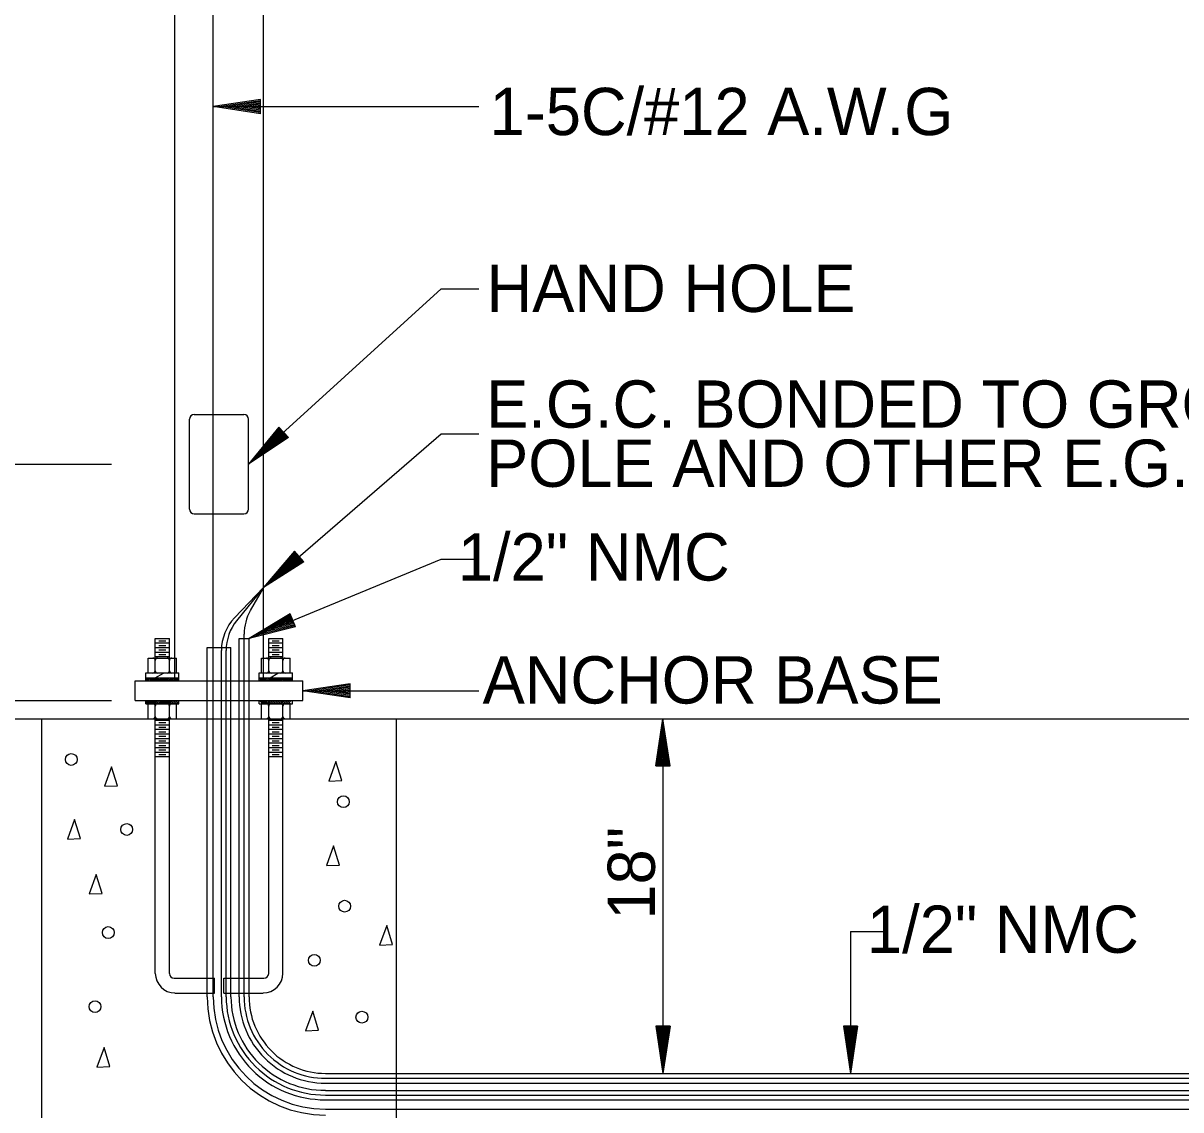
# Model space of a CAD drawing. Extents: x 1369885 to 1370886, y 379976 to 380616.
# Drawn here: x 1369995.4 to 1370105.6, y 380406.2 to 380509.6 of the extents above; entities that cross this region are included whole.
import ezdxf

# ---------------------------------------------------------------- set-up
doc = ezdxf.new("R2010")
doc.units = 0
doc.layers.add('R_Draft', color=7, linetype='Continuous')

msp = doc.modelspace()

# ---------------------------------------------------------------- linework, layer by layer
at = {"layer": 'R_Draft'}
for p, q in [((1370009.8, 380447), (1370009.8, 380537.68)), ((1370018.24, 380447), (1370018.24, 380537.68)), ((1370013.45, 380416.95), (1370013.45, 380515.9)), ((1370017.96, 380502.33), (1370013.46, 380501.65)), ((1370017.96, 380502.21), (1370014.21, 380501.65)), ((1370017.96, 380502.1), (1370014.98, 380501.65)), ((1370017.96, 380501.99), (1370015.73, 380501.65)), ((1370017.96, 380501.87), (1370016.5, 380501.65)), ((1370017.96, 380500.98), (1370017.96, 380502.33)), ((1370013.46, 380501.65), (1370038.75, 380501.65)), ((1370017.96, 380500.98), (1370013.46, 380501.65)), ((1370017.96, 380501.09), (1370014.21, 380501.65)), ((1370017.96, 380501.2), (1370014.98, 380501.65)), ((1370017.96, 380501.32), (1370015.73, 380501.65)), ((1370017.96, 380501.43), (1370016.5, 380501.65)), ((1370017.96, 380501.76), (1370017.25, 380501.65)), ((1370017.96, 380501.55), (1370017.25, 380501.65)), ((1370016.83, 380467.63), (1370035.14, 380484.32)), ((1370035.14, 380484.32), (1370038.75, 380484.32)), ((1370011.65, 380472.35), (1370016.38, 380472.35)), ((1370011.2, 380463.35), (1370011.2, 380471.9)), ((1370016.83, 380463.35), (1370016.83, 380471.9)), ((1370019.7, 380471.16), (1370016.83, 380467.63)), ((1370019.77, 380471.08), (1370017.38, 380468.14)), ((1370019.85, 380470.99), (1370017.96, 380468.66)), ((1370020.61, 380470.16), (1370019.7, 380471.16)), ((1370020.61, 380470.16), (1370016.83, 380467.63)), ((1370020.53, 380470.25), (1370017.38, 380468.14)), ((1370020.45, 380470.33), (1370017.96, 380468.66)), ((1370018.24, 380455.89), (1370035.14, 380470.51)), ((1370019.93, 380470.91), (1370018.51, 380469.16)), ((1370020.38, 380470.42), (1370018.51, 380469.16)), ((1370020, 380470.83), (1370019.07, 380469.68)), ((1370020.3, 380470.5), (1370019.07, 380469.68)), ((1370020.08, 380470.74), (1370019.63, 380470.18)), ((1370020.22, 380470.59), (1370019.63, 380470.18)), ((1370035.14, 380470.51), (1370038.75, 380470.51)), ((1369990.67, 380467.63), (1370003.78, 380467.63)), ((1370011.65, 380462.9), (1370016.38, 380462.9)), ((1370021.18, 380459.36), (1370018.24, 380455.89)), ((1370021.25, 380459.28), (1370018.8, 380456.38)), ((1370021.33, 380459.19), (1370019.38, 380456.89)), ((1370021.4, 380459.11), (1370019.95, 380457.39)), ((1370021.48, 380459.02), (1370020.52, 380457.89)), ((1370021.55, 380458.93), (1370021.09, 380458.38)), ((1370022.07, 380458.35), (1370021.18, 380459.36)), ((1370016.87, 380451.05), (1370035.14, 380458.59)), ((1370022.07, 380458.35), (1370018.24, 380455.89)), ((1370021.99, 380458.43), (1370018.8, 380456.38)), ((1370021.92, 380458.52), (1370019.38, 380456.89)), ((1370021.84, 380458.6), (1370019.95, 380457.39)), ((1370021.76, 380458.69), (1370020.52, 380457.89)), ((1370021.69, 380458.77), (1370021.09, 380458.38)), ((1370035.14, 380458.59), (1370038.75, 380458.59)), ((1370018.24, 380455.89), (1370015.49, 380453.01)), ((1370018.24, 380455.89), (1370015.69, 380452.73)), ((1370018.24, 380455.89), (1370016.98, 380453.69)), ((1370020.77, 380453.39), (1370016.87, 380451.05)), ((1370021.28, 380452.14), (1370020.77, 380453.39)), ((1370020.81, 380453.29), (1370017.56, 380451.34)), ((1370021.24, 380452.25), (1370017.56, 380451.34)), ((1370020.86, 380453.18), (1370018.28, 380451.63)), ((1370021.2, 380452.35), (1370018.28, 380451.63)), ((1370020.9, 380453.08), (1370018.97, 380451.92)), ((1370021.15, 380452.46), (1370018.97, 380451.92)), ((1370020.94, 380452.97), (1370019.67, 380452.21)), ((1370021.11, 380452.57), (1370019.67, 380452.21)), ((1370020.99, 380452.87), (1370020.37, 380452.5)), ((1370021.07, 380452.67), (1370020.37, 380452.5)), ((1370016.4, 380416.95), (1370016.4, 380451.46)), ((1370021.28, 380452.14), (1370016.87, 380451.05)), ((1370007.94, 380451.05), (1370009.29, 380451.05)), ((1370007.94, 380449.18), (1370007.94, 380451.05)), ((1370007.94, 380450.62), (1370009.29, 380450.62)), ((1370007.94, 380450.19), (1370009.29, 380450.19)), ((1370008.28, 380450.83), (1370008.95, 380450.83)), ((1370008.28, 380450.39), (1370008.95, 380450.39)), ((1370009.29, 380449.18), (1370009.29, 380451.05)), ((1370012.89, 380416.95), (1370012.89, 380450.19)), ((1370012.89, 380450.19), (1370015.14, 380450.19)), ((1370015.14, 380416.95), (1370015.14, 380450.19)), ((1370015.93, 380416.95), (1370015.93, 380451.05)), ((1370015.93, 380451.05), (1370016.87, 380451.05)), ((1370016.87, 380416.95), (1370016.87, 380451.05)), ((1370018.74, 380451.05), (1370020.09, 380451.05)), ((1370018.74, 380449.18), (1370018.74, 380451.05)), ((1370018.74, 380450.62), (1370020.09, 380450.62)), ((1370018.74, 380450.19), (1370020.09, 380450.19)), ((1370019.08, 380450.83), (1370019.75, 380450.83)), ((1370019.08, 380450.39), (1370019.75, 380450.39)), ((1370020.09, 380449.18), (1370020.09, 380451.05)), ((1370007.27, 380447.76), (1370007.27, 380449.18)), ((1370007.27, 380449.18), (1370009.97, 380449.18)), ((1370007.94, 380449.75), (1370009.29, 380449.75)), ((1370007.94, 380449.32), (1370009.29, 380449.32)), ((1370007.94, 380447.76), (1370007.94, 380449.18)), ((1370008.28, 380449.96), (1370008.95, 380449.96)), ((1370008.28, 380449.53), (1370008.95, 380449.53)), ((1370009.29, 380447.76), (1370009.29, 380449.18)), ((1370009.97, 380447.76), (1370009.97, 380449.18)), ((1370014.24, 380416.95), (1370014.24, 380449.9)), ((1370014.69, 380416.95), (1370014.69, 380449.91)), ((1370018.07, 380447.76), (1370018.07, 380449.18)), ((1370018.07, 380449.18), (1370020.77, 380449.18)), ((1370018.74, 380449.75), (1370020.09, 380449.75)), ((1370018.74, 380449.32), (1370020.09, 380449.32)), ((1370018.74, 380447.76), (1370018.74, 380449.18)), ((1370019.08, 380449.96), (1370019.75, 380449.96)), ((1370019.08, 380449.53), (1370019.75, 380449.53)), ((1370020.09, 380447.76), (1370020.09, 380449.18)), ((1370020.77, 380447.76), (1370020.77, 380449.18)), ((1370006.03, 380445.13), (1370006.03, 380447)), ((1370006.03, 380447), (1370022, 380447)), ((1370007.04, 380447), (1370007.04, 380447.76)), ((1370007.04, 380447.76), (1370010.19, 380447.76)), ((1370007.04, 380447.3), (1370010.19, 380447.3)), ((1370007.04, 380447.15), (1370007.2, 380447.3)), ((1370007.06, 380447), (1370007.36, 380447.3)), ((1370007.22, 380447), (1370007.52, 380447.3)), ((1370007.38, 380447), (1370007.68, 380447.3)), ((1370007.53, 380447), (1370007.83, 380447.3)), ((1370007.69, 380447), (1370007.94, 380447.25)), ((1370007.85, 380447), (1370007.94, 380447.09)), ((1370007.94, 380447.3), (1370008.73, 380447.74)), ((1370007.94, 380447.07), (1370008.17, 380447.3)), ((1370007.94, 380447.23), (1370008.01, 380447.3)), ((1370008.03, 380447), (1370008.33, 380447.3)), ((1370008.19, 380447), (1370008.49, 380447.3)), ((1370008.35, 380447), (1370008.65, 380447.3)), ((1370008.51, 380447), (1370008.81, 380447.3)), ((1370008.67, 380447), (1370008.97, 380447.3)), ((1370008.83, 380447), (1370009.13, 380447.3)), ((1370008.99, 380447), (1370009.29, 380447.3)), ((1370009.15, 380447), (1370009.29, 380447.15)), ((1370009.29, 380447.12), (1370009.48, 380447.3)), ((1370009.29, 380447.27), (1370009.32, 380447.3)), ((1370009.34, 380447), (1370009.64, 380447.3)), ((1370009.5, 380447), (1370009.8, 380447.3)), ((1370009.66, 380447), (1370009.8, 380447.14)), ((1370009.8, 380447.02), (1370010.08, 380447.3)), ((1370009.8, 380447.18), (1370009.92, 380447.3)), ((1370009.94, 380447), (1370010.19, 380447.25)), ((1370010.1, 380447), (1370010.19, 380447.09)), ((1370010.19, 380447), (1370010.19, 380447.76)), ((1370017.84, 380447), (1370017.84, 380447.76)), ((1370017.84, 380447.76), (1370020.99, 380447.76)), ((1370017.84, 380447.3), (1370020.99, 380447.3)), ((1370017.87, 380447), (1370018.17, 380447.3)), ((1370017.9, 380447.18), (1370018.02, 380447.3)), ((1370018.03, 380447), (1370018.24, 380447.21)), ((1370018.19, 380447), (1370018.24, 380447.05)), ((1370018.24, 380447.1), (1370018.44, 380447.3)), ((1370018.24, 380447.25), (1370018.28, 380447.3)), ((1370018.3, 380447), (1370018.6, 380447.3)), ((1370018.46, 380447), (1370018.74, 380447.28)), ((1370018.62, 380447), (1370018.74, 380447.12)), ((1370018.74, 380447.08), (1370018.96, 380447.3)), ((1370018.74, 380447.24), (1370018.8, 380447.3)), ((1370018.82, 380447), (1370019.12, 380447.3)), ((1370018.88, 380447.3), (1370019.62, 380447.75)), ((1370018.98, 380447), (1370019.28, 380447.3)), ((1370019.14, 380447), (1370019.44, 380447.3)), ((1370019.3, 380447), (1370019.6, 380447.3)), ((1370019.46, 380447), (1370019.76, 380447.3)), ((1370019.62, 380447), (1370019.92, 380447.3)), ((1370019.78, 380447), (1370020.08, 380447.3)), ((1370019.94, 380447), (1370020.09, 380447.16)), ((1370020.09, 380447.13), (1370020.26, 380447.3)), ((1370020.09, 380447.29), (1370020.1, 380447.3)), ((1370020.12, 380447), (1370020.42, 380447.3)), ((1370020.28, 380447), (1370020.58, 380447.3)), ((1370020.44, 380447), (1370020.74, 380447.3)), ((1370020.6, 380447), (1370020.9, 380447.3)), ((1370020.76, 380447), (1370020.94, 380447.18)), ((1370020.92, 380447), (1370020.97, 380447.06)), ((1370020.99, 380447), (1370020.99, 380447.76)), ((1370022, 380445.13), (1370022, 380447)), ((1370026.5, 380446.74), (1370022, 380446.07)), ((1370026.5, 380445.39), (1370026.5, 380446.74)), ((1370022, 380446.07), (1370038.75, 380446.07)), ((1370026.5, 380445.39), (1370022, 380446.07)), ((1370026.5, 380446.63), (1370022.76, 380446.07)), ((1370026.5, 380445.5), (1370022.76, 380446.07)), ((1370026.5, 380446.51), (1370023.53, 380446.07)), ((1370026.5, 380445.62), (1370023.53, 380446.07)), ((1370026.5, 380446.4), (1370024.28, 380446.07)), ((1370026.5, 380445.73), (1370024.28, 380446.07)), ((1370026.5, 380446.29), (1370025.04, 380446.07)), ((1370026.5, 380445.85), (1370025.04, 380446.07)), ((1370026.5, 380446.17), (1370025.79, 380446.07)), ((1370026.5, 380445.96), (1370025.79, 380446.07)), ((1369990.67, 380445.13), (1370003.78, 380445.13)), ((1370006.03, 380445.13), (1370022, 380445.13)), ((1370007.04, 380444.83), (1370007.04, 380445.13)), ((1370007.04, 380444.98), (1370007.19, 380445.13)), ((1370007.04, 380444.83), (1370010.19, 380444.83)), ((1370007.05, 380444.83), (1370007.35, 380445.13)), ((1370007.21, 380444.83), (1370007.51, 380445.13)), ((1370007.27, 380443.41), (1370007.27, 380444.83)), ((1370007.37, 380444.83), (1370007.67, 380445.13)), ((1370007.53, 380444.83), (1370007.83, 380445.13)), ((1370007.69, 380444.83), (1370007.94, 380445.08)), ((1370007.85, 380444.83), (1370007.94, 380444.92)), ((1370007.94, 380444.9), (1370008.17, 380445.13)), ((1370007.94, 380445.06), (1370008.01, 380445.13)), ((1370007.94, 380443.41), (1370007.94, 380444.83)), ((1370008.03, 380444.83), (1370008.33, 380445.13)), ((1370008.19, 380444.83), (1370008.49, 380445.13)), ((1370008.35, 380444.83), (1370008.65, 380445.13)), ((1370008.51, 380444.83), (1370008.81, 380445.13)), ((1370008.67, 380444.83), (1370008.97, 380445.13)), ((1370008.83, 380444.83), (1370009.13, 380445.13)), ((1370008.99, 380444.83), (1370009.29, 380445.13)), ((1370009.15, 380444.83), (1370009.29, 380444.97)), ((1370009.29, 380444.83), (1370009.59, 380445.13)), ((1370009.29, 380444.99), (1370009.43, 380445.13)), ((1370009.29, 380443.41), (1370009.29, 380444.83)), ((1370009.45, 380444.83), (1370009.75, 380445.13)), ((1370009.61, 380444.83), (1370009.91, 380445.13)), ((1370009.77, 380444.83), (1370010.07, 380445.13)), ((1370009.93, 380444.83), (1370010.19, 380445.09)), ((1370009.97, 380443.41), (1370009.97, 380444.83)), ((1370010.09, 380444.83), (1370010.19, 380444.93)), ((1370010.19, 380444.83), (1370010.19, 380445.13)), ((1370017.84, 380444.83), (1370017.84, 380445.13)), ((1370017.84, 380444.83), (1370020.99, 380444.83)), ((1370017.85, 380445.12), (1370017.86, 380445.13)), ((1370017.92, 380445.03), (1370018.01, 380445.13)), ((1370017.98, 380444.94), (1370018.17, 380445.13)), ((1370018.05, 380444.85), (1370018.33, 380445.13)), ((1370018.07, 380443.41), (1370018.07, 380444.83)), ((1370018.19, 380444.83), (1370018.49, 380445.13)), ((1370018.35, 380444.83), (1370018.65, 380445.13)), ((1370018.51, 380444.83), (1370018.74, 380445.06)), ((1370018.67, 380444.83), (1370018.74, 380444.9)), ((1370018.74, 380444.89), (1370018.98, 380445.13)), ((1370018.74, 380445.05), (1370018.82, 380445.13)), ((1370018.74, 380443.41), (1370018.74, 380444.83)), ((1370018.84, 380444.83), (1370019.14, 380445.13)), ((1370019, 380444.83), (1370019.3, 380445.13)), ((1370019.16, 380444.83), (1370019.46, 380445.13)), ((1370019.32, 380444.83), (1370019.62, 380445.13)), ((1370019.48, 380444.83), (1370019.78, 380445.13)), ((1370019.64, 380444.83), (1370019.94, 380445.13)), ((1370019.79, 380444.83), (1370020.09, 380445.13)), ((1370019.95, 380444.83), (1370020.09, 380444.97)), ((1370020.09, 380444.97), (1370020.25, 380445.13)), ((1370020.09, 380445.13), (1370020.09, 380445.13)), ((1370020.09, 380443.41), (1370020.09, 380444.83)), ((1370020.11, 380444.83), (1370020.41, 380445.13)), ((1370020.27, 380444.83), (1370020.57, 380445.13)), ((1370020.43, 380444.83), (1370020.73, 380445.13)), ((1370020.59, 380444.83), (1370020.89, 380445.13)), ((1370020.75, 380444.83), (1370020.82, 380444.9)), ((1370020.77, 380443.41), (1370020.77, 380444.83)), ((1370020.99, 380444.83), (1370020.99, 380445.13)), ((1369937.36, 380443.41), (1370175.16, 380443.41)), ((1369997.14, 380375.91), (1369997.14, 380443.41)), ((1369997.14, 380443.41), (1370030.89, 380443.41)), ((1370007.27, 380443.41), (1370009.97, 380443.41)), ((1370007.94, 380419.18), (1370007.94, 380443.41)), ((1370007.94, 380443.26), (1370009.29, 380443.26)), ((1370007.94, 380442.83), (1370009.29, 380442.83)), ((1370007.94, 380442.4), (1370009.29, 380442.4)), ((1370008.28, 380443.04), (1370008.95, 380443.04)), ((1370008.28, 380442.61), (1370008.95, 380442.61)), ((1370009.29, 380419.16), (1370009.29, 380443.41)), ((1370018.07, 380443.41), (1370020.77, 380443.41)), ((1370018.74, 380419.16), (1370018.74, 380443.41)), ((1370018.74, 380443.26), (1370020.09, 380443.26)), ((1370018.74, 380442.83), (1370020.09, 380442.83)), ((1370018.74, 380442.4), (1370020.09, 380442.4)), ((1370019.08, 380443.04), (1370019.75, 380443.04)), ((1370019.08, 380442.61), (1370019.75, 380442.61)), ((1370020.09, 380419.18), (1370020.09, 380443.41)), ((1370030.89, 380375.91), (1370030.89, 380443.41)), ((1370055.59, 380438.91), (1370056.26, 380443.41)), ((1370055.7, 380438.91), (1370056.26, 380442.66)), ((1370056.26, 380443.41), (1370056.26, 380409.66)), ((1370056.94, 380438.91), (1370056.26, 380443.41)), ((1370056.82, 380438.91), (1370056.26, 380442.66)), ((1370007.94, 380441.97), (1370009.29, 380441.97)), ((1370007.94, 380441.53), (1370009.29, 380441.53)), ((1370008.28, 380442.17), (1370008.95, 380442.17)), ((1370008.28, 380441.74), (1370008.95, 380441.74)), ((1370008.28, 380441.31), (1370008.95, 380441.31)), ((1370018.74, 380441.97), (1370020.09, 380441.97)), ((1370018.74, 380441.53), (1370020.09, 380441.53)), ((1370019.08, 380442.17), (1370019.75, 380442.17)), ((1370019.08, 380441.74), (1370019.75, 380441.74)), ((1370019.08, 380441.31), (1370019.75, 380441.31)), ((1370055.81, 380438.91), (1370056.26, 380441.88)), ((1370056.71, 380438.91), (1370056.26, 380441.88)), ((1370007.94, 380441.1), (1370009.29, 380441.1)), ((1370007.94, 380440.67), (1370009.29, 380440.67)), ((1370007.94, 380440.23), (1370009.29, 380440.23)), ((1370008.28, 380440.87), (1370008.95, 380440.87)), ((1370008.28, 380440.44), (1370008.95, 380440.44)), ((1370018.74, 380441.1), (1370020.09, 380441.1)), ((1370018.74, 380440.67), (1370020.09, 380440.67)), ((1370018.74, 380440.23), (1370020.09, 380440.23)), ((1370019.08, 380440.87), (1370019.75, 380440.87)), ((1370019.08, 380440.44), (1370019.75, 380440.44)), ((1370055.93, 380438.91), (1370056.26, 380441.13)), ((1370056.04, 380438.91), (1370056.26, 380440.37)), ((1370056.6, 380438.91), (1370056.26, 380441.13)), ((1370056.48, 380438.91), (1370056.26, 380440.37)), ((1370007.94, 380439.8), (1370009.29, 380439.8)), ((1370008.28, 380440.01), (1370008.95, 380440.01)), ((1370018.74, 380439.8), (1370020.09, 380439.8)), ((1370019.08, 380440.01), (1370019.75, 380440.01)), ((1370056.16, 380438.91), (1370056.26, 380439.62)), ((1370056.37, 380438.91), (1370056.26, 380439.62)), ((1370055.59, 380438.91), (1370056.94, 380438.91)), ((1370074.12, 380423.17), (1370074.12, 380409.66)), ((1370074.12, 380423.17), (1370077.69, 380423.17)), ((1370009.74, 380418.71), (1370013.57, 380418.71)), ((1370013.57, 380417.3), (1370013.57, 380418.71)), ((1370014.47, 380417.3), (1370014.47, 380418.71)), ((1370014.47, 380418.71), (1370018.29, 380418.71)), ((1370009.82, 380417.3), (1370013.57, 380417.3)), ((1370014.47, 380417.3), (1370018.22, 380417.3)), ((1370055.59, 380414.16), (1370056.26, 380409.66)), ((1370056.94, 380414.16), (1370055.59, 380414.16)), ((1370055.7, 380414.16), (1370056.26, 380410.41)), ((1370055.81, 380414.16), (1370056.26, 380411.18)), ((1370055.93, 380414.16), (1370056.26, 380411.93)), ((1370056.04, 380414.16), (1370056.26, 380412.69)), ((1370056.16, 380414.16), (1370056.26, 380413.45)), ((1370056.94, 380414.16), (1370056.26, 380409.66)), ((1370056.48, 380414.16), (1370056.26, 380412.69)), ((1370056.71, 380414.16), (1370056.26, 380411.18)), ((1370056.82, 380414.16), (1370056.26, 380410.41)), ((1370056.6, 380414.16), (1370056.26, 380411.93)), ((1370056.37, 380414.16), (1370056.26, 380413.45)), ((1370073.44, 380414.16), (1370074.12, 380409.66)), ((1370074.79, 380414.16), (1370073.44, 380414.16)), ((1370073.56, 380414.16), (1370074.12, 380410.41)), ((1370073.67, 380414.16), (1370074.12, 380411.18)), ((1370073.78, 380414.16), (1370074.12, 380411.93)), ((1370073.9, 380414.16), (1370074.12, 380412.69)), ((1370074.01, 380414.16), (1370074.12, 380413.45)), ((1370074.79, 380414.16), (1370074.12, 380409.66)), ((1370074.34, 380414.16), (1370074.12, 380412.69)), ((1370074.57, 380414.16), (1370074.12, 380411.18)), ((1370074.68, 380414.16), (1370074.12, 380410.41)), ((1370074.45, 380414.16), (1370074.12, 380411.93)), ((1370074.22, 380414.16), (1370074.12, 380413.45)), ((1370024.14, 380409.66), (1370135.45, 380409.66)), ((1370024.14, 380409.19), (1370134.34, 380409.19)), ((1370024.14, 380408.72), (1370135.45, 380408.72)), ((1370024.14, 380408.04), (1370135.45, 380408.04)), ((1370024.14, 380407.59), (1370141.69, 380407.59)), ((1370024.14, 380407.14), (1370138.42, 380407.14)), ((1370024.14, 380406.26), (1370135.45, 380406.26))]:
    msp.add_line(p, q, dxfattribs=at)
for points in [[(1370025.14, 380439.35), (1370024.45, 380437.48), (1370025.69, 380437.53), (1370025.14, 380439.35)], [(1370003.79, 380438.84), (1370003.11, 380436.98), (1370004.35, 380437.03), (1370003.79, 380438.84)], [(1370000.27, 380433.81), (1369999.59, 380431.95), (1370000.83, 380432), (1370000.27, 380433.81)], [(1370024.91, 380431.3), (1370024.23, 380429.43), (1370025.47, 380429.48), (1370024.91, 380431.3)], [(1370002.32, 380428.6), (1370001.64, 380426.73), (1370002.88, 380426.78), (1370002.32, 380428.6)], [(1370029.97, 380423.73), (1370029.29, 380421.86), (1370030.53, 380421.91), (1370029.97, 380423.73)], [(1370022.94, 380415.58), (1370022.25, 380413.72), (1370023.49, 380413.77), (1370022.94, 380415.58)], [(1370003.07, 380412.12), (1370002.39, 380410.26), (1370003.63, 380410.31), (1370003.07, 380412.12)]]:
    msp.add_lwpolyline(points, dxfattribs=at)
for centre in [(1369999.95, 380439.53), (1370025.85, 380435.51), (1370005.23, 380432.87), (1370025.97, 380425.57), (1370003.47, 380423.06), (1370023.08, 380420.42), (1370002.21, 380416.01), (1370027.61, 380415.01)]:
    msp.add_circle(centre, 0.562, dxfattribs=at)
for centre, radius, start, end in [((1370011.65, 380471.9), 0.45, 90, 180), ((1370016.38, 380471.9), 0.45, 360, 90), ((1370011.65, 380463.35), 0.45, 180, 270), ((1370016.38, 380463.35), 0.45, 270, 0), ((1370020.9, 380451.46), 4.5, 150.4069, 180), ((1370018.74, 380449.9), 4.5, 136.323, 180), ((1370019.19, 380449.91), 4.5, 141.118, 180), ((1370007.72, 380448.95), 0.225, 0, 90), ((1370008.17, 380448.95), 0.225, 90, 180), ((1370009.07, 380448.95), 0.225, 0, 90), ((1370009.52, 380448.95), 0.225, 90, 180), ((1370018.52, 380448.95), 0.225, 0, 90), ((1370018.97, 380448.95), 0.225, 90, 180), ((1370019.87, 380448.95), 0.225, 0, 90), ((1370020.32, 380448.95), 0.225, 90, 180), ((1370007.72, 380447.98), 0.225, 270, 0), ((1370008.17, 380447.98), 0.225, 180, 270), ((1370009.07, 380447.98), 0.225, 270, 0), ((1370009.52, 380447.98), 0.225, 180, 270), ((1370018.52, 380447.98), 0.225, 270, 0), ((1370018.97, 380447.98), 0.225, 180, 270), ((1370019.87, 380447.98), 0.225, 270, 0), ((1370020.32, 380447.98), 0.225, 180, 270), ((1370007.72, 380444.6), 0.225, 0, 90), ((1370008.17, 380444.6), 0.225, 90, 180), ((1370009.07, 380444.6), 0.225, 0, 90), ((1370009.52, 380444.6), 0.225, 90, 180), ((1370018.52, 380444.6), 0.225, 0, 90), ((1370018.97, 380444.6), 0.225, 90, 180), ((1370019.87, 380444.6), 0.225, 0, 90), ((1370020.32, 380444.6), 0.225, 90, 180), ((1370007.72, 380443.63), 0.225, 270, 0), ((1370008.17, 380443.63), 0.225, 180, 270), ((1370009.07, 380443.63), 0.225, 270, 0), ((1370009.52, 380443.63), 0.225, 180, 270), ((1370018.52, 380443.63), 0.225, 270, 0), ((1370018.97, 380443.63), 0.225, 180, 270), ((1370019.87, 380443.63), 0.225, 270, 0), ((1370020.32, 380443.63), 0.225, 180, 270), ((1370009.82, 380419.18), 1.87, 180, 270), ((1370009.74, 380419.16), 0.45, 180, 270), ((1370018.22, 380419.18), 1.87, 270, 0), ((1370018.29, 380419.16), 0.45, 270, 0), ((1370024.14, 380416.95), 11.25, 180, 270), ((1370024.14, 380416.95), 10.69, 180, 270), ((1370024.09, 380417), 9.85, 180.3, 270.3), ((1370024.09, 380417), 9.4, 180.3, 270.3), ((1370024.09, 380417), 8.95, 180.3, 270.3), ((1370024.15, 380416.94), 8.22, 179.9347, 269.9347), ((1370024.15, 380416.94), 7.75, 179.9263, 269.9263), ((1370024.15, 380416.94), 7.28, 179.9263, 269.9263)]:
    msp.add_arc(centre, radius, start, end, dxfattribs=at)

# ---------------------------------------------------------------- texts
for s, p in [('1-5C/#12 A.W.G', (1370039.76, 380498.94)), ('HAND HOLE', (1370039.48, 380482.11)), ('E.G.C. BONDED TO GROUND LUG ON ', (1370039.43, 380471.1)), ('POLE AND OTHER E.G.C. CONDUCTORS', (1370039.43, 380465.47)), (' 1/2" NMC ', (1370035.07, 380456.55)), ('ANCHOR BASE', (1370039.1, 380444.85)), (' 1/2" NMC ', (1370074.01, 380421.13))]:
    msp.add_text(s, height=4.5, dxfattribs=at).set_placement(p)
msp.add_text('18"', height=4.5, rotation=90, dxfattribs=at).set_placement((1370055.5, 380424.29))

doc.saveas('drawing.dxf')
